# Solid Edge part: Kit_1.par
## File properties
Author: bmolnar
Last saved by: bmolnar
Revision: 77
Sűrűség: 0,000 kg/m^3
Pontosság: 0,990
Username: bmolnar
Dokumentum tartalom típus: 0
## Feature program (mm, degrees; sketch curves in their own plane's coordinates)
base feature "unnamed BaseFeature 1"
sketch for "unnamed Cutout 1" plane through (0, -0.0012, 85.05) normal (0, 0, -1) x-axis (-1, 0, 0)
  circle centre (0, 0.0012) radius 6
extrude "unnamed Cutout 1" cut through along -normal
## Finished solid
Body 1: solid body, 48 faces, 65 edges, 51 vertices, 1 internal void.
  Faces by surface: cone 15, cylinder 15, plane 14, torus 4
  Edges by curve: circle 47, line 18
Bounding box of the edges (mm; curved faces can reach further): 35.700 x 35.450 x 9.450, from (-17.85, -16.85, 85.05) to (17.85, 18.6, 94.5).
Cylindrical faces by radius (mm): R1.25 x2, R2.25 x2, R6 x1, R6.27 x1, R6.85 x1, R7 x1, R8.16 x1, R8.25 x1, R11.5 x1, R12.25 x1, R15.9 x1, R16.85 x1, R17.85 x1
Conical faces (half-angle, radius in mm at the cone's reference point): 3 deg R8.205 x1, 7 deg R7.5925 x1, 14 deg R6.135 x1, 14 deg R6.4811 x1, 17 deg R6.135 x1, 23 deg R6.829 x1, 30 deg R11.875 x1, 42.5 deg R6.1233 x1, 45 deg R7.1 x2, 45 deg R11.75 x1, 84 deg R59.397 x2, 85 deg R7.9463 x1, 87 deg R6.1765 x1
Toroidal faces (ring radius, tube radius in mm): R6.8057 r0.2025 x1, R7.2522 r0.2925 x1, R7.96 r0.2 x1, R11.9 r0.4 x1
Planar faces by outward normal: +z 7, -z 3, oblique 4
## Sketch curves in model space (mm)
circle centre (0, 0, 85.05) radius 6
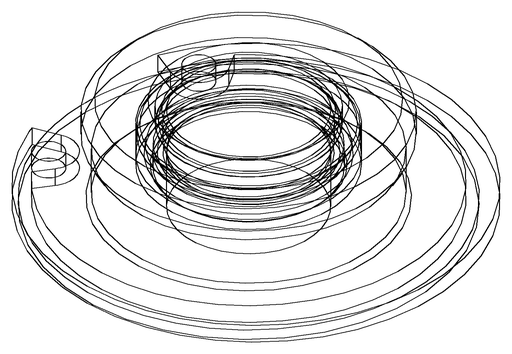
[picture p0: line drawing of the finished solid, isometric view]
